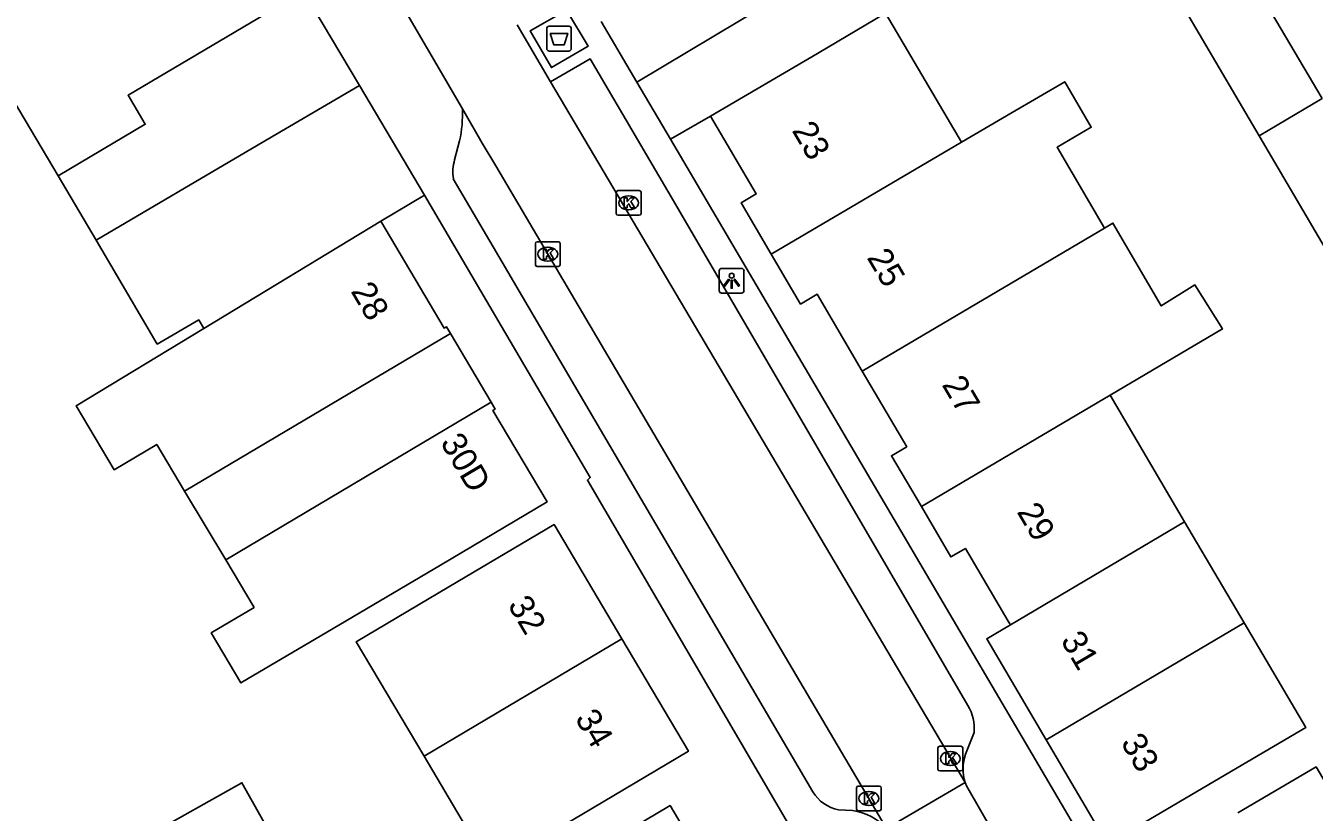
# Model space of a CAD drawing. Extents: x 159718 to 160783, y 383290 to 384030.
# Drawn here: x 160162.9 to 160214.9, y 383342.6 to 383374.3 of the extents above; entities that cross this region are included whole.
import ezdxf

# ---------------------------------------------------------------- set-up
doc = ezdxf.new("R2010")
doc.units = 0
for name, color, linetype in [('IMGEO_Afval_apart_plaats', 7, 'Continuous'), ('IMGEO_Erf', 7, 'Continuous'), ('IMGEO_Groenvoorziening', 7, 'Continuous'), ('IMGEO_Kolk', 7, 'Continuous'), ('IMGEO_Lichtpunt', 7, 'Continuous'), ('IMGEO_Pand', 7, 'Continuous'), ('IMGEO_Pand_nummerreeks', 7, 'Continuous'), ('IMGEO_Pand_overbouw', 7, 'Continuous'), ('IMGEO_Rijbaan_lokaal_open', 7, 'Continuous'), ('IMGEO_Voetpad_gesloten', 7, 'Continuous'), ('IMGEO_Voetpad_open', 7, 'Continuous')]:
    doc.layers.add(name, color=color, linetype=linetype)

msp = doc.modelspace()

# ---------------------------------------------------------------- linework, layer by layer
at = {"layer": 'IMGEO_Afval_apart_plaats'}
for p, q in [((160183.934, 383373.407), (160183.934, 383374.207)), ((160183.934, 383374.207), (160183.934, 383373.407)), ((160184.034, 383374.307), (160184.824, 383374.307)), ((160184.824, 383374.307), (160184.034, 383374.307)), ((160184.924, 383374.207), (160184.924, 383373.407)), ((160184.924, 383373.407), (160184.924, 383374.207)), ((160184.824, 383373.307), (160184.034, 383373.307)), ((160184.034, 383373.307), (160184.824, 383373.307))]:
    msp.add_line(p, q, dxfattribs=at)
msp.add_lwpolyline([(160184.077, 383374.021), (160184.781, 383374.021), (160184.632, 383373.551), (160184.226, 383373.551), (160184.077, 383374.021)], dxfattribs=at)
for centre, start, end in [((160184.034, 383374.207), 90, 180), ((160184.034, 383374.207), 90, 180), ((160184.824, 383374.207), 0, 90), ((160184.824, 383374.207), 360, 90), ((160184.034, 383373.407), 180, 270), ((160184.034, 383373.407), 180, 270), ((160184.824, 383373.407), 270, 0), ((160184.824, 383373.407), 270, 0)]:
    msp.add_arc(centre, 0.1, start, end, dxfattribs=at)
at = {"layer": 'IMGEO_Erf'}
msp.add_lwpolyline([(160165.756, 383365.67), (160164.216, 383368.269)], dxfattribs=at)
at = {"layer": 'IMGEO_Groenvoorziening'}
msp.add_lwpolyline([(160190.544, 383370.673), (160188.923, 383369.749)], dxfattribs=at)
at = {"layer": 'IMGEO_Kolk'}
for p, q in [((160186.814, 383367.681), (160187.666, 383367.681)), ((160186.739, 383366.755), (160186.739, 383367.607)), ((160187.227, 383367.461), (160187.252, 383367.461)), ((160187.74, 383367.607), (160187.74, 383366.755)), ((160187.666, 383366.681), (160186.814, 383366.681)), ((160187.25, 383366.901), (160187.225, 383366.901)), ((160183.551, 383365.613), (160184.403, 383365.613)), ((160183.476, 383364.687), (160183.476, 383365.539)), ((160183.964, 383365.393), (160183.989, 383365.393)), ((160184.477, 383365.539), (160184.477, 383364.687)), ((160184.403, 383364.613), (160183.551, 383364.613)), ((160183.987, 383364.833), (160183.962, 383364.833)), ((160199.719, 383344.335), (160199.719, 383345.187)), ((160199.794, 383345.261), (160200.646, 383345.261)), ((160200.207, 383345.041), (160200.232, 383345.041)), ((160200.72, 383345.187), (160200.72, 383344.335)), ((160200.23, 383344.481), (160200.205, 383344.481)), ((160200.646, 383344.261), (160199.794, 383344.261)), ((160196.433, 383342.724), (160196.433, 383343.576)), ((160196.508, 383343.65), (160197.36, 383343.65)), ((160196.921, 383343.43), (160196.946, 383343.43)), ((160197.434, 383343.576), (160197.434, 383342.724)), ((160196.944, 383342.87), (160196.919, 383342.87)), ((160197.36, 383342.65), (160196.508, 383342.65))]:
    msp.add_line(p, q, dxfattribs=at)
for points in [[(160186.814, 383367.681), (160187.666, 383367.681)], [(160186.739, 383366.755), (160186.739, 383367.607)], [(160187.06, 383367.381), (160187.183, 383367.381), (160187.183, 383367.23), (160187.313, 383367.381), (160187.477, 383367.381), (160187.331, 383367.23), (160187.484, 383366.981), (160187.332, 383366.981), (160187.247, 383367.145), (160187.183, 383367.078), (160187.183, 383366.981), (160187.06, 383366.981), (160187.06, 383367.381)], [(160187.74, 383367.607), (160187.74, 383366.755)], [(160187.666, 383366.681), (160186.814, 383366.681)], [(160183.551, 383365.613), (160184.403, 383365.613)], [(160183.476, 383364.687), (160183.476, 383365.539)], [(160183.797, 383365.313), (160183.92, 383365.313), (160183.92, 383365.162), (160184.05, 383365.313), (160184.214, 383365.313), (160184.068, 383365.162), (160184.221, 383364.913), (160184.069, 383364.913), (160183.984, 383365.077), (160183.92, 383365.01), (160183.92, 383364.913), (160183.797, 383364.913), (160183.797, 383365.313)], [(160184.477, 383365.539), (160184.477, 383364.687)], [(160184.403, 383364.613), (160183.551, 383364.613)], [(160199.719, 383344.335), (160199.719, 383345.187)], [(160199.794, 383345.261), (160200.646, 383345.261)], [(160200.04, 383344.961), (160200.163, 383344.961), (160200.163, 383344.81), (160200.293, 383344.961), (160200.457, 383344.961), (160200.311, 383344.81), (160200.464, 383344.561), (160200.312, 383344.561), (160200.227, 383344.725), (160200.163, 383344.658), (160200.163, 383344.561), (160200.04, 383344.561), (160200.04, 383344.961)], [(160200.72, 383345.187), (160200.72, 383344.335)], [(160200.646, 383344.261), (160199.794, 383344.261)], [(160196.433, 383342.724), (160196.433, 383343.576)], [(160196.508, 383343.65), (160197.36, 383343.65)], [(160196.754, 383343.35), (160196.877, 383343.35), (160196.877, 383343.199), (160197.007, 383343.35), (160197.171, 383343.35), (160197.025, 383343.199), (160197.178, 383342.95), (160197.026, 383342.95), (160196.941, 383343.114), (160196.877, 383343.047), (160196.877, 383342.95), (160196.754, 383342.95), (160196.754, 383343.35)], [(160197.434, 383343.576), (160197.434, 383342.724)], [(160197.36, 383342.65), (160196.508, 383342.65)]]:
    msp.add_lwpolyline(points, dxfattribs=at)
for centre, start, end in [((160186.816, 383367.605), 91.552, 178.448), ((160186.816, 383367.605), 91.552, 178.448), ((160187.664, 383367.605), 1.552, 88.448), ((160187.664, 383367.605), 1.552, 88.448), ((160186.816, 383366.757), 181.552, 268.448), ((160186.816, 383366.757), 181.552, 268.448), ((160187.664, 383366.757), 271.552, 358.448), ((160187.664, 383366.757), 271.552, 358.448), ((160183.553, 383365.537), 91.552, 178.448), ((160183.553, 383365.537), 91.552, 178.448), ((160184.401, 383365.537), 1.552, 88.448), ((160184.401, 383365.537), 1.552, 88.448), ((160183.553, 383364.689), 181.552, 268.448), ((160183.553, 383364.689), 181.552, 268.448), ((160184.401, 383364.689), 271.552, 358.448), ((160184.401, 383364.689), 271.552, 358.448), ((160199.796, 383345.185), 91.552, 178.448), ((160199.796, 383345.185), 91.552, 178.448), ((160200.644, 383345.185), 1.552, 88.448), ((160200.644, 383345.185), 1.552, 88.448), ((160199.796, 383344.337), 181.552, 268.448), ((160199.796, 383344.337), 181.552, 268.448), ((160200.644, 383344.337), 271.552, 358.448), ((160200.644, 383344.337), 271.552, 358.448), ((160196.51, 383343.574), 91.552, 178.448), ((160196.51, 383343.574), 91.552, 178.448), ((160197.358, 383343.574), 1.552, 88.448), ((160197.358, 383343.574), 1.552, 88.448), ((160196.51, 383342.726), 181.552, 268.448), ((160196.51, 383342.726), 181.552, 268.448), ((160197.358, 383342.726), 271.552, 358.448), ((160197.358, 383342.726), 271.552, 358.448)]:
    msp.add_arc(centre, 0.0765, start, end, dxfattribs=at)
for centre, major_axis, ratio, start_param, end_param in [((160187.226, 383367.181), (-0.387, 0.002), 0.722429, 4.712389, 7.853982), ((160187.251, 383367.181), (-0.39, 0.002), 0.717154, 1.570796, 4.712389), ((160183.963, 383365.113), (-0.387, 0.002), 0.722429, 4.712389, 7.853982), ((160183.988, 383365.113), (-0.39, 0.002), 0.717154, 1.570796, 4.712389), ((160200.206, 383344.761), (-0.387, 0.002), 0.722429, 4.712389, 7.853982), ((160200.231, 383344.761), (-0.39, 0.002), 0.717154, 1.570796, 4.712389), ((160196.92, 383343.15), (-0.387, 0.002), 0.722429, 4.712389, 7.853982), ((160196.945, 383343.15), (-0.39, 0.002), 0.717154, 1.570796, 4.712389)]:
    msp.add_ellipse(centre, major_axis=major_axis, ratio=ratio, start_param=start_param, end_param=end_param, dxfattribs=at)
at = {"layer": 'IMGEO_Lichtpunt'}
for p, q in [((160190.898, 383364.444), (160190.898, 383363.637)), ((160190.898, 383364.444), (160190.898, 383363.637)), ((160191.8, 383364.539), (160190.992, 383364.539)), ((160191.8, 383364.539), (160190.992, 383364.539)), ((160191.894, 383363.637), (160191.894, 383364.444)), ((160191.894, 383363.637), (160191.894, 383364.444)), ((160190.992, 383363.543), (160191.8, 383363.543)), ((160190.992, 383363.543), (160191.8, 383363.543))]:
    msp.add_line(p, q, dxfattribs=at)
for points in [[(160191.272, 383364.108), (160191.311, 383364.08), (160191.123, 383363.818), (160191.085, 383363.845), (160191.272, 383364.108)], [(160191.374, 383364.06), (160191.421, 383364.06), (160191.421, 383363.738), (160191.374, 383363.738), (160191.374, 383364.06)], [(160191.484, 383364.08), (160191.522, 383364.107), (160191.709, 383363.845), (160191.67, 383363.817), (160191.484, 383364.08)]]:
    msp.add_lwpolyline(points, dxfattribs=at)
msp.add_circle((160191.397, 383364.242), 0.0994, dxfattribs=at)
for centre, start, end in [((160190.992, 383364.444), 90, 180), ((160190.992, 383364.444), 90, 180), ((160191.8, 383364.444), 0, 90), ((160191.8, 383364.444), 0, 90), ((160190.992, 383363.637), 180, 270), ((160190.992, 383363.637), 180, 270), ((160191.8, 383363.637), 270, 0), ((160191.8, 383363.637), 270, 360)]:
    msp.add_arc(centre, 0.0946, start, end, dxfattribs=at)
at = {"layer": 'IMGEO_Pand'}
for points in [[(160164.216, 383368.269), (160153.609, 383386.161)], [(160212.271, 383376.413), (160215.229, 383371.387)], [(160164.216, 383368.269), (160167.736, 383370.356), (160167.042, 383371.525), (160174.12, 383375.721)], [(160197.607, 383374.829), (160194.854, 383373.209), (160190.544, 383370.673)], [(160197.607, 383374.829), (160200.666, 383369.63)], [(160212.677, 383369.885), (160209.719, 383374.911)], [(160176.376, 383371.916), (160172.067, 383369.382), (160165.756, 383365.67)], [(160176.376, 383371.916), (160178.999, 383367.492)], [(160200.666, 383369.63), (160202.72, 383370.829), (160204.837, 383372.065), (160205.907, 383370.232), (160204.528, 383369.427), (160206.435, 383366.161)], [(160215.229, 383371.387), (160212.677, 383369.885)], [(160192.992, 383365.109), (160191.774, 383367.179), (160192.387, 383367.54), (160190.544, 383370.673)], [(160215.705, 383364.74), (160212.677, 383369.885)], [(160200.666, 383369.63), (160192.992, 383365.109)], [(160178.999, 383367.492), (160177.234, 383366.445)], [(160177.234, 383366.445), (160179.795, 383362.127), (160179.885, 383362.181), (160180.048, 383361.905), (160169.32, 383355.543), (160168.198, 383357.436), (160166.477, 383356.416), (160164.947, 383358.996), (160170.095, 383362.117)], [(160170.095, 383362.117), (160177.234, 383366.445)], [(160196.666, 383360.397), (160206.435, 383366.161)], [(160206.435, 383366.161), (160206.78, 383366.365), (160208.731, 383363.025), (160210.088, 383363.872), (160211.199, 383362.093), (160206.673, 383359.423)], [(160170.095, 383362.117), (160169.891, 383362.461), (160168.218, 383361.485), (160165.756, 383365.67)], [(160196.666, 383360.397), (160194.844, 383363.493), (160194.175, 383363.099), (160192.992, 383365.109)], [(160199.052, 383354.927), (160197.845, 383356.979), (160198.463, 383357.343), (160196.666, 383360.397)], [(160206.673, 383359.423), (160199.052, 383354.927)], [(160206.673, 383359.423), (160209.676, 383354.318)], [(160170.981, 383352.785), (160181.69, 383359.135), (160181.853, 383358.86), (160181.76, 383358.805), (160183.946, 383355.118), (160179.646, 383352.568), (160175.316, 383350.008), (160171.594, 383347.81), (160170.395, 383349.833), (160172.123, 383350.859), (160170.981, 383352.785)], [(160202.645, 383350.161), (160202.558, 383350.308), (160200.831, 383353.242), (160200.246, 383352.898), (160199.052, 383354.927)], [(160178.985, 383344.855), (160176.248, 383349.472), (160179.981, 383351.685), (160184.228, 383354.204), (160186.966, 383349.586)], [(160202.645, 383350.161), (160209.676, 383354.318)], [(160209.676, 383354.318), (160212.079, 383350.234)], [(160204.09, 383345.513), (160201.688, 383349.595), (160202.645, 383350.161)], [(160212.079, 383350.234), (160214.563, 383346.013), (160210.875, 383343.843), (160206.565, 383341.307), (160204.09, 383345.513)], [(160204.09, 383345.513), (160212.079, 383350.234)], [(160186.966, 383349.586), (160189.651, 383345.057), (160185.351, 383342.507), (160181.671, 383340.325), (160178.985, 383344.855)], [(160186.966, 383349.586), (160178.985, 383344.855)], [(160211.817, 383342.566), (160214.979, 383344.426), (160216.78, 383341.366), (160213.619, 383339.506)], [(160169.228, 383339.071), (160167.793, 383341.628), (160171.637, 383343.785), (160173.021, 383341.32)], [(160185.722, 383340.972), (160188.909, 383342.861), (160190.734, 383339.781), (160187.548, 383337.892)]]:
    msp.add_lwpolyline(points, dxfattribs=at)
at = {"layer": 'IMGEO_Pand_overbouw'}
for points in [[(160176.376, 383371.916), (160174.12, 383375.721), (160167.042, 383371.525), (160167.736, 383370.356), (160164.216, 383368.269), (160165.756, 383365.67), (160172.067, 383369.382)], [(160180.048, 383361.905), (160169.32, 383355.543), (160170.981, 383352.785), (160181.69, 383359.135)]]:
    msp.add_lwpolyline(points, close=True, dxfattribs=at)
at = {"layer": 'IMGEO_Rijbaan_lokaal_open'}
for points in [[(160180.532, 383370.974), (160177.537, 383376.126), (160177.078, 383376.916)], [(160182.74, 383374.363), (160184.085, 383372.06)], [(160184.085, 383372.06), (160200.823, 383343.792)], [(160180.532, 383370.974), (160181.334, 383369.594), (160181.878, 383368.671), (160197.651, 383341.936)], [(160197.651, 383341.936), (160200.823, 383343.792)], [(160200.823, 383343.792), (160200.887, 383343.627), (160200.975, 383343.477), (160202.907, 383340.129)]]:
    msp.add_lwpolyline(points, dxfattribs=at)
at = {"layer": 'IMGEO_Voetpad_gesloten'}
msp.add_lwpolyline([(160184.732, 383374.953), (160185.601, 383373.498), (160184.12, 383372.637), (160183.259, 383374.116), (160184.732, 383374.953)], dxfattribs=at)
at = {"layer": 'IMGEO_Voetpad_open'}
for points in [[(160187.571, 383372.047), (160207.249, 383383.817)], [(160174.12, 383375.721), (160176.376, 383371.916)], [(160186.126, 383374.501), (160187.571, 383372.047)], [(160184.085, 383372.06), (160185.683, 383372.991), (160189.051, 383367.258), (160200.924, 383346.903)], [(160188.923, 383369.749), (160187.571, 383372.047)], [(160180.217, 383368.923), (160180.417, 383369.68)], [(160188.923, 383369.749), (160213.993, 383327.146)], [(160194.678, 383343.421), (160181.776, 383365.405), (160180.165, 383368.149)], [(160209.871, 383314.427), (160185.573, 383355.997), (160185.693, 383356.097), (160178.999, 383367.492)], [(160201.178, 383345.811), (160200.836, 383344.935)], [(160196.278, 383342.66), (160195.707, 383342.698)]]:
    msp.add_lwpolyline(points, dxfattribs=at)
for centre, radius, start, end in [((160175.241, 383370.792), 5.295, 347.8744, 1.9683), ((160182.024, 383368.413), 1.877, 164.2338, 188.0791), ((160199.513, 383345.999), 1.676, 353.5514, 32.637), ((160202.492, 383344.345), 1.758, 160.374, 198.3227), ((160195.978, 383344.177), 1.504, 210.1935, 259.6209), ((160195.961, 383340.396), 2.286, 42.3517, 82.0419)]:
    msp.add_arc(centre, radius, start, end, dxfattribs=at)

# ---------------------------------------------------------------- texts
at = {"layer": 'IMGEO_Pand_nummerreeks'}
for s, rotation, p in [('23', 300.5374, (160193.807, 383370.102)), ('25', 300.5374, (160196.832, 383364.974)), ('28', 300.6702, (160176.004, 383363.619)), ('27', 300.5374, (160199.857, 383359.846)), ('30D', 300.6645, (160179.619, 383357.514)), ('29', 300.5384, (160202.883, 383354.718)), ('32', 300.6625, (160182.339, 383350.958)), ('31', 300.4754, (160204.651, 383349.529)), ('34', 300.6625, (160185.052, 383346.382)), ('33', 300.4759, (160207.076, 383345.406))]:
    msp.add_text(s, height=1, rotation=rotation, dxfattribs=at).set_placement(p)

doc.saveas('drawing.dxf')
